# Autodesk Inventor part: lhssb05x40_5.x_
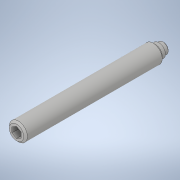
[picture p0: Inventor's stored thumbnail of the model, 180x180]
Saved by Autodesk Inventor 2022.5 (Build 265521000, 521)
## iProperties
Created: 2021-02
Part Number: lhssb05x40_5.x_
Material: 一般
Document SubType Name: Modeling
Designer: ImaoCorp
Density: 1 g/cm^3
Appearance: 既定
Sending System: SOLIDWORKS 2019-2019304
MC: AMD64
MC_MODEL: Intel64 Family 6 Model 60 Stepping 3, GenuineIntel
OS: Windows_NT
FRU: Parasolid Version 31.0, build 290,  9- 1-2019
FORMAT: text
GUISE: transmit
KEY: lhssb05x40_5
FILE: lhssb05x40_5.x_t
DATE: Mon Feb 22 14:56:16 2021
Author: ImaoCorp
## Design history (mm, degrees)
feature "Base1"
node "ソリッド1"
